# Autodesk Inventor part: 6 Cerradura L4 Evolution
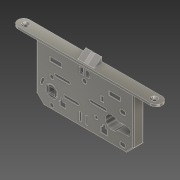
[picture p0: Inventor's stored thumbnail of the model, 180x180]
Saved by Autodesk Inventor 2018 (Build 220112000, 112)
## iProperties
Created: 2019-09
Part Number: 6 Cerradura L4 Evolution
Material: Acero inoxidable
Document SubType Name: Modeling
Designer: Alfredo Castillo
Mass: 72.3663 g
Surface Area: 73.8223 cm^2
Volume: 9.04579 cm^3
Density: 8 g/cm^3
Appearance: Semipulido
Author: Alfredo Castillo
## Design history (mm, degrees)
sketch "Boceto2"
  geometry: L1 (0, 0)-(-196, 0); L2 (-8, 8)-(-188, 8); L3 (-188, -8)-(-8, -8); C1 r 2.5 at (-10.5, 0); C2 r 2.5 at (-185.5, 0); A1 r 8 centre (-8, 0) between (-8, -8) and (-8, 8); A2 r 8 centre (-188, 0) between (-188, 8) and (-188, -8); 1 further point
  constraints: 8 end point, 6 point on circle, 4 centre point, 4 point on line, 4 tangent, 1 horizontal, 1 midpoint, 1 parallel
  dimensions: "d6" = 196 distance of L1.start L1.end; "d7" = 16 diameter of A2; "d8" = 5 diameter of C1; "d9" = 5 diameter of C2; "d10" = 175 distance of C1.centre C2.centre; "d11" = 10.5 distance of L1.end C2.centre
extrude "Extrusión2" new body sketch "Boceto2" distance "d12" = 3; taper "d13" = 0 deg
chamfer "Chaflán1" distance "d14" = 2; stored, may be unused: second distance "d15" = 2, angle "d16" = 45 deg
chamfer "Chaflán2" distance "d17" = 2; stored, may be unused: second distance "d18" = 2, angle "d19" = 45 deg
sketch "Boceto3"
  geometry: L1 (32, -7)-(164, -7); L2 (164, -7)-(164, 7); L3 (164, 7)-(32, 7); L4 (32, 7)-(32, -7); L5 (188, -8)-(8, -8) reference; 1 further point
  constraints: 8 end point, 2 parallel, 1 horizontal, 1 perpendicular
  dimensions: "d20" = 132 distance of L3.end L2.end; "d21" = 14 distance of L2.end L1.end; "d22" = 32 distance from line of point (0, 0) L4; "d23" = 1 distance between parallel lines of L5 L1
extrude "Extrusión3" join sketch "Boceto3" distance "d24" = 73; taper "d25" = 0 deg
chamfer "Chaflán3" distance "d26" = 10; stored, may be unused: second distance "d27" = 2, angle "d28" = 45 deg
fillet "Empalme1" dims "d29" = 1
fillet "Empalme2" dims "d30" = 1
sketch "Boceto4"
  geometry: L1 (-87, 5.5)-(-109, 5.5); L2 (-109, 5.5)-(-109, -5.5); L3 (-109, -5.5)-(-87, -5.5); L4 (-87, -5.5)-(-87, 5.5); L5 (-8, 8)-(-188, 8) reference; L6 (-86.75, 5.75)-(-109.25, 5.75); L7 (-109.25, 5.75)-(-109.25, -5.75); L8 (-109.25, -5.75)-(-86.75, -5.75); L9 (-86.75, -5.75)-(-86.75, 5.75); 1 further point
  constraints: 16 end point, 4 parallel, 2 perpendicular, 1 horizontal, 3 other
  dimensions: "d31" = 22 distance of L3.end L2.end; "d32" = 11 distance of L2.end L1.end; "d33" = 87 distance from line of point (0, 0) L4; "d34" = 2.5 distance between parallel lines of L5 L1; "d35" = 0.25 distance between parallel lines of L4 L9
node "Plano de trabajo1"
sketch "Boceto5"
  geometry: L1 (13.5, 0)-(-2.5, 0) reference; L2 (11, 0)-(11, 7.945); L3 (11, 0)-(18.945, 0); L4 (10.183, 8.332)-(0, 0); L5 (0, 0)-(11, 0) reference; A1 r 0.5 centre (10.5, 7.945) between (11, 7.945) and (10.183, 8.332); 4 further points
  constraints: 6 end point, 2 point on circle, 2 point on line, 2 tangent, 1 centre point, 1 horizontal, 1 perpendicular, 1 vertical
  dimensions: "d39" = 9 distance of L2.start point (11, 9); "d40" = 90 deg angle of L3 L2 (derived); "d41" = 0.5 radius of A1
extrude "Extrusión4" join sketch "Boceto5" distance "d42" = 22; taper "d43" = 0 deg
extrude "Extrusión5" cut sketch "Boceto4" distance "d44" = 2; taper "d45" = 0 deg
sketch "Boceto6"
  geometry: L1 (17.514, -17.419)-(33.514, -17.419); L2 (33.514, -17.419)-(33.514, -11.419); L3 (33.514, -11.419)-(17.514, -11.419); L4 (17.514, -11.419)-(17.514, -17.419); L5 (97.792, -17.493)-(112.792, -17.493); L6 (112.792, -17.493)-(112.792, -11.493); L7 (112.792, -11.493)-(97.792, -11.493); L8 (97.792, -11.493)-(97.792, -17.493); L9 (35.808, -48.701)-(57.263, -48.701); L10 (37.808, -50.701)-(55.263, -50.701); L11 (55.263, -46.701)-(37.808, -46.701); L12 (23.214, -29.792)-(45.214, -29.792); L13 (25.214, -31.792)-(43.214, -31.792); L14 (43.214, -27.792)-(25.214, -27.792); L15 (58.677, -68.137)-(58.677, -55.768); L16 (57.131, -66.591)-(57.131, -57.314); L17 (60.223, -57.314)-(60.223, -66.591); L18 (70.731, -36.651)-(94.767, -36.651); L19 (72.665, -34.717)-(92.833, -34.717); L20 (92.833, -38.585)-(72.665, -38.585); L21 (30.839, -62.949)-(39, -62.949); L22 (39, -62.949)-(39, -56.462); L23 (39, -56.462)-(34.92, -56.462); L24 (34.92, -56.462)-(34.92, -53.915); L25 (31.936, -53.915)-(31.936, -56.462); L26 (31.936, -56.462)-(30.839, -56.462); L27 (30.839, -56.462)-(30.839, -57.314); L28 (30.839, -57.314)-(30.211, -57.314); L29 (30.211, -58.602)-(30.839, -58.602); L30 (30.839, -58.602)-(30.839, -62.949); L31 (86.844, -66.602)-(95.155, -66.602); L32 (95.155, -66.602)-(95.155, -58.602); L33 (95.155, -58.602)-(93.155, -58.602); L34 (86.844, -66.602)-(86.844, -58.602); L35 (86.844, -58.602)-(88.844, -58.602); L36 (88.844, -58.602)-(88.844, -56.888); L37 (93.155, -56.888)-(93.155, -58.602); L38 (111.949, -27.937)-(120.449, -27.937); L39 (114.949, -30.937)-(117.449, -30.937); L40 (117.449, -24.937)-(114.949, -24.937); L41 (57.501, -11.555)-(71.678, -11.555); L42 (71.678, -11.555)-(71.678, -2.972); L43 (71.678, -2.972)-(57.501, -2.972); L44 (57.501, -2.972)-(57.501, -11.555); L45 (128.656, -37.593)-(128.656, -57.593); L46 (128.656, -57.593)-(126.535, -59.715); L47 (126.535, -59.715)-(103.656, -59.715); L48 (103.656, -59.715)-(103.656, -37.593); L49 (103.656, -37.593)-(128.656, -37.593); L50 (117.449, -63.19)-(114.949, -63.19); L51 (114.949, -69.19)-(117.449, -69.19); L52 (111.949, -66.19)-(120.449, -66.19); L53 (67.562, -68.137)-(67.562, -55.768); L54 (66.016, -66.591)-(66.016, -57.314); L55 (69.108, -57.314)-(69.108, -66.591); L56 (86.844, -29.792)-(90.844, -29.792); L57 (90.844, -29.792)-(90.844, -22.792); L58 (90.844, -22.792)-(86.844, -22.792); L59 (86.844, -22.792)-(86.844, -29.792); C1 r 3 at (19.742, -68.014); C2 r 3 at (19.742, -34.41); C3 r 3.306 at (64.256, -17.446); C4 r 2.547 at (80.376, -51.976); C5 r 7.5 at (19.742, -51.368); A1 r 2 centre (37.808, -48.701) between (37.808, -46.701) and (37.808, -50.701); A2 r 2 centre (55.263, -48.701) between (55.263, -50.701) and (55.263, -46.701); A3 r 2 centre (25.214, -29.792) between (25.214, -27.792) and (25.214, -31.792); A4 r 2 centre (43.214, -29.792) between (43.214, -31.792) and (43.214, -27.792); A5 r 1.546 centre (58.677, -66.591) between (57.131, -66.591) and (60.223, -66.591); A6 r 1.546 centre (58.677, -57.314) between (60.223, -57.314) and (57.131, -57.314); A7 r 1.934 centre (72.665, -36.651) between (72.665, -34.717) and (72.665, -38.585); A8 r 1.934 centre (92.833, -36.651) between (92.833, -38.585) and (92.833, -34.717); A9 r 1.492 centre (33.428, -53.915) between (34.92, -53.915) and (31.936, -53.915); A10 r 0.644 centre (30.211, -57.958) between (30.211, -57.314) and (30.211, -58.602); A11 r 14.143 centre (19.742, -51.368) between (8.767, -42.448) and (5.777, -49.13); A12 r 15.893 centre (19.742, -51.368) between (7.409, -41.344) and (4.05, -48.853); A13 r 12.393 centre (19.742, -51.368) between (10.125, -43.552) and (7.505, -49.407); A14 r 1.75 centre (8.767, -42.448) between (10.125, -43.552) and (7.409, -41.344); A15 r 1.75 centre (5.777, -49.13) between (4.05, -48.853) and (7.505, -49.407); A16 r 2.155 centre (90.999, -56.888) between (93.155, -56.888) and (88.844, -56.888); A17 r 3 centre (114.949, -27.937) between (114.949, -24.937) and (114.949, -30.937); A18 r 3 centre (117.449, -27.937) between (117.449, -30.937) and (117.449, -24.937); A19 r 3 centre (114.949, -66.19) between (114.949, -63.19) and (114.949, -69.19); A20 r 3 centre (117.449, -66.19) between (117.449, -69.19) and (117.449, -63.19); A21 r 1.546 centre (67.562, -66.591) between (66.016, -66.591) and (69.108, -66.591); A22 r 1.546 centre (67.562, -57.314) between (69.108, -57.314) and (66.016, -57.314); 8 further points
  constraints: 132 end point, 58 point on circle, 38 tangent, 27 centre point, 18 parallel, 18 perpendicular, 15 point on line, 9 horizontal, 7 midpoint, 4 vertical, 1 coincident
  dimensions: "d46" = 15 diameter of C5; "d47" = 3.5 diameter of A15; "d48" = 2 distance of L34.end L35.end; "d49" = 2 distance of L32.end L33.end; "d51" = 8 distance of L31.start L34.end; "d52" = 8 distance of L31.end L32.end; "d53" = 6 diameter of A18; "d54" = 2.5 distance of A18.centre A17.centre; "d55" = 15 distance of L5.start L5.end; "d56" = 16 distance of L1.start L1.end; "d57" = 4 distance between parallel lines of L10 L11; "d58" = 4 distance between parallel lines of L14 L13; "d59" = 6 diameter of C1; "d60" = 6 diameter of C2; "d61" = 30 deg dimension on C5.centre A11.start A11.end; "d62" = 6 distance of L7.end L5.start; "d63" = 20 distance of L45.start L45.end; "d64" = 3 distance of L45.end L46.end; "d65" = 135 deg angle of L45 L46; "d66" = 6 diameter of A20; "d67" = 2.5 distance of A20.centre A19.centre; "d68" = 25 distance of L48.end L45.start; "d69" = 4 distance of L58.end L57.end; "d70" = 7 distance of L57.end L56.end; "d124" = 6 distance of L3.end L1.start
extrude "Extrusión6" cut sketch "Boceto6" distance "d71" = 1; taper "d72" = 0 deg
sketch "Boceto7"
  geometry: L1 (-3.5, -3.5)-(3.5, -3.5); L2 (3.5, -3.5)-(3.5, 3.5); L3 (3.5, 3.5)-(-3.5, 3.5); L4 (-3.5, 3.5)-(-3.5, -3.5); L5 (-3.5, -3.5)-(3.5, 3.5); L6 (3.5, -3.5)-(-3.5, 3.5); C1 r 4 at (94.6, 7.999); 2 further points
  constraints: 12 end point, 2 midpoint, 2 parallel, 1 centre point, 1 horizontal, 1 perpendicular
  dimensions: "d73" = 7 distance of L3.end L2.end; "d74" = 7 distance of L2.end L1.end; "d75" = 8 diameter of C1
extrude "Extrusión7" cut sketch "Boceto7" distance "d76" = 20; taper "d77" = 0 deg
sketch "Boceto8"
  geometry: L1 (3.5, 3.5)-(3.5, -3.5) reference; L2 (3.5, -3.5)-(-3.5, -3.5) reference; L3 (-3.5, -3.5)-(-3.5, 3.5) reference; L4 (-3.5, 3.5)-(3.5, 3.5) reference; C1 r 7.5 at (0, 0) reference; C2 r 4.5 at (91.99, 7.5); 1 further point
  constraints: 1 centre point
  dimensions: "d78" = 9 diameter of C2
extrude "Extrusión8" join sketch "Boceto8" distance "d79" = 1; taper "d80" = 0 deg
sketch "Boceto9"
  geometry: L1 (-3.5, -3.5)-(-3.5, 3.5) reference; L2 (-3.5, 3.5)-(3.5, 3.5) reference; L3 (3.5, 3.5)-(3.5, -3.5) reference; L4 (3.5, -3.5)-(-3.5, -3.5) reference; C1 r 7.5 at (0, 0) reference; C2 r 7.25 at (0, 0); 1 further point
  constraints: 1 centre point, 1 coincident
  dimensions: "d81" = 14.5 diameter of C2
extrude "Extrusión9" join sketch "Boceto9" distance "d82" = 1; taper "d83" = 0 deg
fillet "Empalme3" dims "d84" = 1
chamfer "Chaflán4" distance "d85" = 1; stored, may be unused: second distance "d86" = 2, angle "d87" = 45 deg
fillet "Empalme4" dims "d88" = 1
sketch "Boceto10"
  geometry: L1 (-2.25, -2.25)-(2.25, -2.25); L2 (2.25, -2.25)-(2.25, 2.25); L3 (2.25, 2.25)-(-2.25, 2.25); L4 (-2.25, 2.25)-(-2.25, -2.25); L5 (-2.25, -2.25)-(2.25, 2.25); L6 (2.25, -2.25)-(-2.25, 2.25); 2 further points
  constraints: 12 end point, 2 midpoint, 2 parallel, 1 horizontal, 1 perpendicular
  dimensions: "d89" = 4.5 distance of L3.end L2.end; "d90" = 4.5 distance of L2.end L1.end
extrude "Extrusión10" cut sketch "Boceto10" distance "d91" = 20; taper "d92" = 0 deg
sketch "Boceto11"
  geometry: L1 (57.501, -11.555)-(57.501, -2.972) reference; L2 (71.678, -11.555)-(57.501, -11.555) reference; L3 (71.678, -11.555)-(57.501, -11.555) reference; L4 (71.678, -2.972)-(71.678, -11.555) reference; L5 (57.501, -2.972)-(71.678, -2.972) reference; L6 (57.501, -11.555)-(57.501, -2.972) reference; 1 further point
extrude "Extrusión11" cut sketch "Boceto11" distance "d93" = 2.5; taper "d94" = 0 deg
sketch "Boceto12"
  geometry: L1 (57.501, -2.972)-(71.678, -2.972) reference; L2 (71.678, -11.555)-(57.501, -11.555) reference; L3 (63.501, -11.555)-(63.501, -2.972); L4 (66.001, -11.555)-(66.001, -2.972); L5 (57.037, -11.555)-(57.037, -2.972); L6 (63.501, -11.555)-(66.001, -11.555); L7 (63.501, -2.972)-(66.001, -2.972); 1 further point
  constraints: 10 end point, 2 parallel, 2 point on line, 1 collinear, 1 horizontal, 1 vertical
  dimensions: "d95" = 2.5 distance between parallel lines of L3 L4; "d97" = 14.17619 distance of L1.start L1.end (derived)
extrude "Extrusión12" join sketch "Boceto12" distance "d98" = 3.5; taper "d99" = 0 deg
fillet "Empalme5" dims "d100" = 2
fillet "Empalme6" dims "d101" = 1
fillet "Empalme7" dims "d102" = 0.5
sketch "Boceto13"
  geometry: L1 (103.656, -59.715)-(103.656, -37.593) reference; L2 (126.535, -59.715)-(103.656, -59.715) reference; L3 (128.656, -57.593)-(126.535, -59.715) reference; L4 (128.656, -37.593)-(128.656, -57.593) reference; L5 (103.656, -37.593)-(128.656, -37.593) reference; 1 further point
extrude "Extrusión13" join sketch "Boceto13" distance "d103" = 1; taper "d104" = 0 deg
sketch "Boceto15"
  geometry: L1 (109.482, 41.618)-(109.482, 46.118) reference; L2 (113.982, 41.618)-(109.482, 41.618) reference; L3 (113.982, 46.118)-(113.982, 41.618) reference; L4 (109.482, 46.118)-(113.982, 46.118) reference; 1 further point
extrude "Extrusión15" join sketch "Boceto15" distance "d109" = 13; taper "d110" = 0 deg
sketch "Boceto18"
  geometry: L1 (127.477, -47.185)-(101.977, -47.185); L2 (121.977, -41.685)-(109.101, -41.685); L3 (109.101, -52.685)-(121.977, -52.685); A1 r 9 centre (101.977, -47.185) between (109.101, -41.685) and (109.101, -52.685); A2 r 5.5 centre (121.977, -47.185) between (121.977, -52.685) and (121.977, -41.685); 4 further points
  constraints: 8 end point, 5 point on circle, 2 centre point, 2 coincident, 2 tangent, 1 midpoint, 1 parallel, 1 point on line
  dimensions: "d125" = 18 diameter of A1; "d126" = 20 distance of A2.centre A1.centre; "d127" = 10 distance of point (111.977, -47.185) A1.centre; "d128" = 11 distance between parallel lines of L2 L3
extrude "Extrusión18" cut sketch "Boceto18" distance "d129" = 15; taper "d130" = 0 deg
sketch "Boceto21"
  geometry: L1 (64.324, 42.701)-(64.324, 57.314); L2 (66.016, 66.591)-(66.016, 57.314); L3 (66.074, 42.701)-(66.074, 57.314); L4 (62.574, 57.314)-(62.574, 42.701); L5 (90.844, 22.792)-(90.844, 29.792); L6 (90.75, 22.503)-(78.797, 23.251); L7 (78.797, 24.749)-(90.844, 25.503); L8 (72.011, 55.804)-(76.852, 55.804); L9 (76.852, 55.804)-(76.852, 58.06); L10 (76.852, 58.06)-(75.777, 59.064); L11 (75.777, 59.064)-(72.011, 59.064); L12 (72.011, 59.064)-(72.011, 55.804); L13 (86.261, 70.5)-(92.261, 70.5); L14 (92.261, 70.5)-(92.261, 66.5); L15 (86.261, 66.5)-(86.261, 70.5); L16 (29.576, 70.5)-(35.576, 70.5); L17 (35.576, 70.5)-(35.576, 66.5); L18 (29.576, 66.5)-(29.576, 70.5); L19 (120.586, 73)-(9.414, 73); L20 (5.011, 2.197)-(5.011, 4.773); L21 (8.875, 2.197)-(5.011, 2.197); L22 (8.875, 4.773)-(8.875, 2.197); L23 (48.547, 4.773)-(48.547, 2.197); L24 (48.547, 2.197)-(44.683, 2.197); L25 (44.683, 2.197)-(44.683, 4.773); L26 (88.685, 4.773)-(88.685, 2.197); L27 (88.685, 2.197)-(84.821, 2.197); L28 (84.821, 2.197)-(84.821, 4.773); L29 (124.45, 4.773)-(124.45, 2.197); L30 (124.45, 2.197)-(120.586, 2.197); L31 (120.586, 2.197)-(120.586, 4.773); L32 (0, 62.586)-(9.414, 72); L33 (130, 0)-(0, 0); L34 (130, 62.586)-(130, 0); L35 (120.586, 72)-(130, 62.586); L36 (9.414, 72)-(120.586, 72); L37 (117.449, 30.937)-(114.949, 30.937); L38 (114.949, 24.937)-(117.449, 24.937); L39 (117.449, 69.19)-(114.949, 69.19); L40 (114.949, 63.19)-(117.449, 63.19); C1 r 6 at (64.297, 7); C2 r 3.306 at (64.256, 17.446); C3 r 1.5 at (98.893, 24); C4 r 3 at (19.742, 34.41); C5 r 3 at (19.742, 68.014); C6 r 2.547 at (80.376, 51.976); A1 r 1.75 centre (64.324, 42.701) between (62.574, 42.701) and (66.074, 42.701); A2 r 1.75 centre (64.324, 57.314) between (66.074, 57.314) and (62.574, 57.314); A3 r 0.75 centre (78.844, 24) between (78.797, 24.749) and (78.797, 23.251); A4 r 1.5 centre (90.844, 24) between (90.75, 22.503) and (90.75, 25.497); A5 r 3 centre (89.261, 66.5) between (86.261, 66.5) and (92.261, 66.5); A6 r 3 centre (32.576, 66.5) between (29.576, 66.5) and (35.576, 66.5); A7 r 1.932 centre (6.943, 4.773) between (8.875, 4.773) and (5.011, 4.773); A8 r 1.932 centre (46.615, 4.773) between (48.547, 4.773) and (44.683, 4.773); A9 r 1.932 centre (86.753, 4.773) between (88.685, 4.773) and (84.821, 4.773); A10 r 1.932 centre (122.518, 4.773) between (124.45, 4.773) and (120.586, 4.773); A11 r 15.893 centre (19.742, 51.368) between (4.05, 48.853) and (7.409, 41.344); A12 r 12.393 centre (19.742, 51.368) between (7.505, 49.407) and (10.125, 43.552); A13 r 1.75 centre (8.767, 42.448) between (7.409, 41.344) and (10.125, 43.552); A14 r 1.75 centre (5.777, 49.13) between (7.505, 49.407) and (4.05, 48.853); A15 r 3 centre (114.949, 27.937) between (114.949, 30.937) and (114.949, 24.937); A16 r 3 centre (117.449, 27.937) between (117.449, 24.937) and (117.449, 30.937); A17 r 3 centre (114.949, 66.19) between (114.949, 69.19) and (114.949, 63.19); A18 r 3 centre (117.449, 66.19) between (117.449, 63.19) and (117.449, 69.19); 1 further point
  constraints: 82 end point, 36 point on circle, 24 centre point, 20 tangent, 5 vertical, 3 horizontal, 3 parallel, 3 point on line, 1 midpoint, 1 perpendicular
  dimensions: "d165" = 12 diameter of C1; "d167" = 3.5 diameter of A2; "d168" = 1.5 diameter of A3; "d169" = 3 diameter of A4; "d172" = 12 distance of A3.centre A4.centre; "d173" = 3 diameter of C3; "d174" = 6 distance of L13.start L13.end; "d175" = 4 distance of L13.end L14.end; "d176" = 6 distance of L16.start L16.end; "d177" = 4 distance of L16.end L17.end; "d178" = 2.5 distance between parallel lines of L19 L13; "d179" = 2.5 distance between parallel lines of L19 L16
extrude "Extrusión21" cut sketch "Boceto21" distance "d180" = 1; taper "d181" = 0 deg
fillet "Empalme10" dims "d182" = 1
node "Plano de trabajo2"
sketch "Boceto22"
  geometry: C1 r 7.5 at (19.742, 51.368) reference; 1 further point
extrude "Extrusión22" cut sketch "Boceto22" distance "d183" = 1; taper "d184" = 0 deg
fillet "Empalme11" dims "d185" = 1
mirror "Simetría1"
fillet "Empalme12" dims "d186" = 1
sketch "Boceto23"
  geometry: L1 (8, -2)-(13, -2); L2 (13, -2)-(13, -10.445); L3 (13, -10.445)-(8, -10.445); L4 (8, -10.445)-(8, -2); L5 (-0.5, 0)-(-0.5, -9.945) reference; L6 (100.5, -2)-(-79.5, -2) reference; L7 (21, -10.445)-(0, -10.445) reference; 1 further point
  constraints: 8 end point, 2 parallel, 1 horizontal, 1 perpendicular
  dimensions: "d187" = 5 distance between parallel lines of L2 L4; "d188" = 8.5 distance between parallel lines of L4 L5; "d189" = 0 distance between parallel lines of L6 L1; "d190" = 0 distance between parallel lines of L7 L3
extrude "Extrusión23" cut sketch "Boceto23" distance "d191" = 15; taper "d192" = 0 deg
sketch "Boceto24"
  geometry: L1 (-0.387, -0.817)-(7.945, -11) reference; L2 (7.945, -11)-(0, -0.25); L3 (0, -0.5)-(0, 0) reference; L4 (7.945, -0.25)-(7.945, -11); L5 (7.945, -11.25)-(7.945, 0.25) reference; L6 (0, -0.25)-(7.945, -0.25); L7 (7.945, 0)-(7.945, -11) reference; 1 further point
  constraints: 6 end point, 1 collinear, 1 midpoint, 1 perpendicular
extrude "Extrusión24" join sketch "Boceto24" stored distance "d193" = 10; taper "d194" = 0 deg
node "Sólido2"
node "Contorno proyectado1"
node "Contorno proyectado2"
other parameters: "d36" = 90 deg, "d120" = 87 deg
